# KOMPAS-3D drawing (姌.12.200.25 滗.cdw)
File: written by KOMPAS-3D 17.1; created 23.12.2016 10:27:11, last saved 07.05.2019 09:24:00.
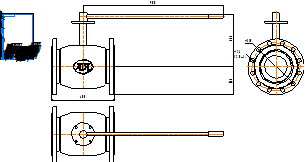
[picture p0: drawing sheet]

Sheet 1: A4, portrait

Title block, sheet 1: name: КШ.12.200.25 фф; material: Внимание! Данный продукт является объектом авторского права ООО «Торговый Дом АДЛ». / Запрещается изменение, копирование, распространение / (в том числе путем копирования на другие сайты и ресурсы в Интернете) / или любое иное использование информации и объектов без предварительного / согласия правообладателя (ООО «Торговый Дом АДЛ»).; sheets: 1; organisation: ООО "Торговый дом АДЛ"; sheet format: A4; stored path: C:\Users\tra\Desktop\2д чертежи\Шаровые краны БИВАЛ\КШ_Бивал_серия_11_12\KOMPAS_2D\КШ.12.200.25 фф.cdw

Views: Вид 1, Проекционный вид 2, Проекционный вид 3
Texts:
  Klimkovich
  ADL
Dimensions and other numbers on the sheet: 400; 336; 180; 310; 900; 26; 12 Отв.; 1:1; 1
